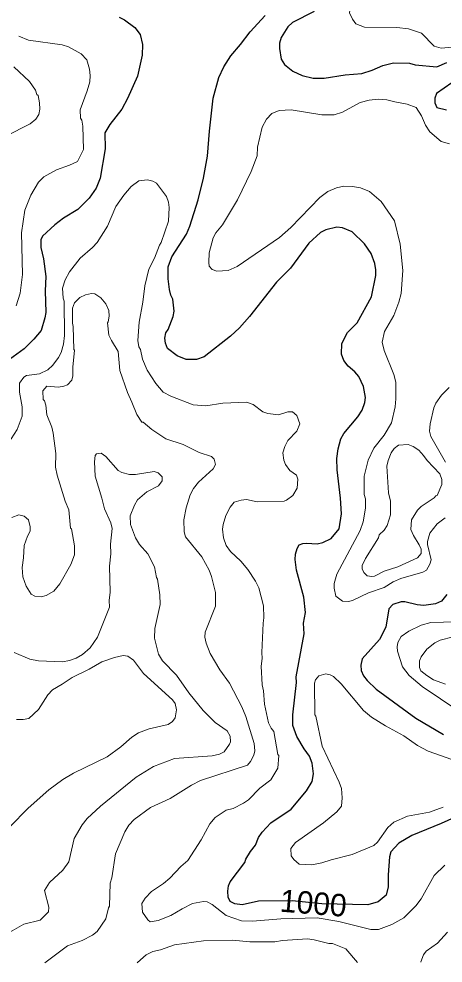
# Model space of a CAD drawing. Extents: x 447.8 to 473.9, y 7733.1 to 7760.8.
# Drawn here: x 467.383 to 468.897, y 7733.127 to 7736.498 of the extents above; entities that cross this region are included whole.
import ezdxf
from ezdxf.enums import TextEntityAlignment as Align

# ---------------------------------------------------------------- set-up
doc = ezdxf.new("R2010")
doc.units = 0
doc.header["$LTSCALE"] = 0.032
doc.layers.add('1', color=7, linetype='Continuous', lineweight=25)
doc.layers.add('2', color=7, linetype='Continuous', lineweight=13)
doc.layers.add('61', color=7, linetype='Continuous')

msp = doc.modelspace()

# ---------------------------------------------------------------- linework, layer by layer
at = {"layer": '1'}
for points in [[(468.208, 7736.4522), (468.262, 7736.5109)], [(468.4364, 7736.5251), (468.359, 7736.4854), (468.3427, 7736.4698), (468.3193, 7736.4314), (468.3136, 7736.4119), (468.3128, 7736.3923), (468.3191, 7736.3545), (468.3312, 7736.3349), (468.3605, 7736.3119), (468.3936, 7736.2967), (468.4329, 7736.2869), (468.4722, 7736.2869), (468.548, 7736.298), (468.6076, 7736.3032), (468.6442, 7736.3147), (468.6819, 7736.3316), (468.7199, 7736.3413), (468.7768, 7736.3398), (468.7972, 7736.3341), (468.8746, 7736.3272), (468.9108, 7736.3429)], [(467.7404, 7736.5048), (467.7593, 7736.4954), (467.7965, 7736.468), (467.8157, 7736.4431), (467.8245, 7736.407), (467.823, 7736.369), (467.8062, 7736.2941), (467.7707, 7736.2144), (467.7502, 7736.1765), (467.7073, 7736.1211), (467.6891, 7736.0917), (467.6906, 7736.0348), (467.6731, 7735.9297), (467.6586, 7735.8941), (467.6339, 7735.8577), (467.5931, 7735.8183), (467.5424, 7735.7871), (467.5114, 7735.7629), (467.4672, 7735.7223), (467.4616, 7735.7096), (467.4614, 7735.6816), (467.4711, 7735.642), (467.4791, 7735.5786), (467.4767, 7735.5273), (467.479, 7735.4497), (467.4759, 7735.4311), (467.4618, 7735.3859), (467.4365, 7735.3546), (467.4019, 7735.3207), (467.3358, 7735.2723)], [(468.0759, 7736.2157), (468.0965, 7736.2886), (468.1148, 7736.3271), (468.1398, 7736.3663), (468.1743, 7736.4065), (468.208, 7736.4522)], [(468.9554, 7736.2885), (468.8741, 7736.2317), (468.8675, 7736.2147), (468.8674, 7736.1981), (468.8744, 7736.1816), (468.9088, 7736.1731)], [(468.1897, 7733.4862), (468.1933, 7733.4981), (468.2095, 7733.5256), (468.2275, 7733.5485), (468.238, 7733.5756), (468.2511, 7733.5947), (468.2825, 7733.6281), (468.3546, 7733.6763), (468.41, 7733.7419), (468.4298, 7733.7752), (468.4345, 7733.8034), (468.4296, 7733.8408), (468.42, 7733.866), (468.4013, 7733.8921), (468.3754, 7733.9363), (468.3608, 7733.9758), (468.3608, 7734.0132), (468.3736, 7734.1286), (468.373, 7734.1497), (468.4008, 7734.3021), (468.3993, 7734.341), (468.4057, 7734.3787), (468.4001, 7734.4333), (468.3735, 7734.5305), (468.3689, 7734.5679), (468.3704, 7734.5872), (468.3762, 7734.6069), (468.3839, 7734.62), (468.3965, 7734.6251), (468.4093, 7734.6267), (468.4477, 7734.6236), (468.4681, 7734.6289), (468.4972, 7734.6431), (468.5259, 7734.6776), (468.5339, 7734.7316), (468.5308, 7734.7875), (468.5193, 7734.8881), (468.5181, 7734.9286), (468.5224, 7734.9636), (468.5322, 7734.9992), (468.5423, 7735.018), (468.5922, 7735.077), (468.6083, 7735.1018), (468.6174, 7735.1281), (468.6197, 7735.147), (468.6131, 7735.1861), (468.5958, 7735.222), (468.5818, 7735.2385), (468.5578, 7735.2587), (468.5424, 7735.2785), (468.534, 7735.301), (468.5355, 7735.339), (468.5558, 7735.3781), (468.59, 7735.4135), (468.6412, 7735.5058), (468.6573, 7735.5827), (468.6573, 7735.6027), (468.653, 7735.6255), (468.6409, 7735.6608), (468.6163, 7735.6954), (468.5724, 7735.7385), (468.5375, 7735.7528), (468.5183, 7735.7545), (468.478, 7735.745), (468.4596, 7735.7356), (468.418, 7735.6979), (468.3527, 7735.6087), (468.3021, 7735.558), (468.2056, 7735.4358), (468.1702, 7735.3956), (468.1377, 7735.3656), (468.0447, 7735.2919), (468.0168, 7735.2818), (467.9795, 7735.2817), (467.9482, 7735.2949), (467.9129, 7735.3217), (467.9062, 7735.3401), (467.904, 7735.3586), (467.9079, 7735.3775), (467.9152, 7735.3893), (467.9334, 7735.4352), (467.9367, 7735.4545), (467.9327, 7735.4979), (467.9249, 7735.5122), (467.9199, 7735.5321), (467.916, 7735.5699), (467.9163, 7735.6136), (467.9287, 7735.6485), (467.981, 7735.7301), (467.9929, 7735.7587), (468.0226, 7735.8527), (468.0418, 7735.9297), (468.0566, 7736.0087), (468.0627, 7736.098), (468.0759, 7736.2157)], [(468.91, 7734.4436), (468.891, 7734.4188), (468.8703, 7734.4095), (468.8282, 7734.404), (468.8046, 7734.4064), (468.76, 7734.4167), (468.7471, 7734.4167), (468.7175, 7734.4074), (468.7039, 7734.3925), (468.693, 7734.3261), (468.67, 7734.2827), (468.6082, 7734.2129), (468.6037, 7734.1904), (468.6045, 7734.1723), (468.6124, 7734.1526), (468.6256, 7734.136), (468.6585, 7734.1047), (468.7994, 7734.0019), (468.8981, 7733.9428)], [(468.9981, 7733.674), (468.8904, 7733.6253), (468.7853, 7733.583), (468.7395, 7733.5555), (468.7106, 7733.5248), (468.7053, 7733.5064), (468.7007, 7733.4421), (468.7014, 7733.3995), (468.6943, 7733.3702), (468.6658, 7733.3464), (468.6285, 7733.3355), (468.464, 7733.339), (468.3587, 7733.3488), (468.2376, 7733.3481), (468.1795, 7733.3356), (468.1533, 7733.3384), (468.1366, 7733.3473), (468.1304, 7733.3629), (468.1292, 7733.3839), (468.1316, 7733.403), (468.1367, 7733.4172), (468.1897, 7733.4862)]]:
    msp.add_lwpolyline(points, dxfattribs=at)
at = {"layer": '2'}
for points in [[(468.6085, 7736.5878), (468.5802, 7736.5583), (468.5657, 7736.5381), (468.5631, 7736.5203), (468.5737, 7736.4975), (468.586, 7736.4805)], [(468.586, 7736.4805), (468.6165, 7736.4688), (468.7315, 7736.468), (468.7741, 7736.4632), (468.8195, 7736.447), (468.8657, 7736.4012), (468.8898, 7736.3943), (468.9285, 7736.3975)], [(467.3822, 7736.4371), (467.417, 7736.4219), (467.5368, 7736.4054), (467.5595, 7736.3989), (467.6051, 7736.3734), (467.6248, 7736.3525), (467.6353, 7736.3189), (467.6377, 7736.2961), (467.6361, 7736.2741), (467.6269, 7736.2414), (467.6018, 7736.1734), (467.6026, 7736.1437), (467.6081, 7736.1366), (467.6115, 7736.1151), (467.6137, 7736.0323), (467.5915, 7735.9896), (467.5631, 7735.9761), (467.5172, 7735.9597), (467.4717, 7735.9341), (467.4534, 7735.9154), (467.425, 7735.8694), (467.4041, 7735.815), (467.3926, 7735.734), (467.3957, 7735.5859), (467.3876, 7735.5186), (467.3731, 7735.4737)], [(467.3361, 7736.0799), (467.4232, 7736.1235), (467.4428, 7736.1399), (467.4541, 7736.1572), (467.4574, 7736.1763), (467.4567, 7736.1983), (467.4515, 7736.2251), (467.4473, 7736.2283), (467.4422, 7736.2436), (467.4202, 7736.2751), (467.3647, 7736.3267)], [(468.0896, 7735.5975), (468.0723, 7735.604), (468.0624, 7735.6157), (468.0604, 7735.6291), (468.0626, 7735.6629), (468.0762, 7735.7163), (468.0862, 7735.7347), (468.1096, 7735.7633), (468.163, 7735.8526), (468.2124, 7735.953), (468.233, 7736.0098), (468.235, 7736.0403), (468.2518, 7736.1121), (468.2668, 7736.1406), (468.2858, 7736.1611), (468.3115, 7736.1707), (468.3548, 7736.1738), (468.4638, 7736.1553), (468.508, 7736.1553), (468.5382, 7736.1648), (468.601, 7736.2001), (468.6334, 7736.2082), (468.6651, 7736.2123), (468.6958, 7736.2098), (468.7244, 7736.2019), (468.7693, 7736.1943), (468.8012, 7736.1821), (468.8201, 7736.1521), (468.8346, 7736.1187), (468.8503, 7736.0947), (468.89, 7736.06), (468.9195, 7736.0519)], [(468.2559, 7734.0995), (468.2509, 7734.1204), (468.2478, 7734.1878), (468.251, 7734.2152), (468.2495, 7734.2358), (468.2543, 7734.3413), (468.2574, 7734.3602), (468.2559, 7734.4028), (468.2392, 7734.4666), (468.2271, 7734.4911), (468.2005, 7734.5329), (468.175, 7734.5624), (468.1387, 7734.5962), (468.1228, 7734.618), (468.1135, 7734.6452), (468.1092, 7734.6763), (468.1116, 7734.6936), (468.1218, 7734.7251), (468.1367, 7734.7555), (468.1517, 7734.773), (468.1758, 7734.7805), (468.1954, 7734.7829), (468.2335, 7734.7743), (468.3292, 7734.7765), (468.3387, 7734.7801), (468.3604, 7734.7963), (468.3762, 7734.8223), (468.3783, 7734.8554), (468.3733, 7734.8689), (468.3499, 7734.8862), (468.334, 7734.9069), (468.3287, 7734.9229), (468.325, 7734.949), (468.332, 7734.9717), (468.3433, 7734.9931), (468.3746, 7735.0262), (468.3854, 7735.0523), (468.3749, 7735.0817), (468.3596, 7735.0949), (468.3434, 7735.0957), (468.3098, 7735.0845), (468.2713, 7735.0893), (468.2537, 7735.0956), (468.2189, 7735.1221), (468.1956, 7735.13), (468.1104, 7735.1261), (468.0506, 7735.1173), (468.0046, 7735.1206), (467.925, 7735.1509), (467.8978, 7735.1651), (467.8717, 7735.197), (467.8411, 7735.2439), (467.8241, 7735.2839), (467.8166, 7735.3179), (467.8115, 7735.3275), (467.8078, 7735.3496), (467.8118, 7735.4153), (467.8254, 7735.4874), (467.8325, 7735.5458), (467.8463, 7735.6047), (467.8673, 7735.6445), (467.8848, 7735.6907), (467.8911, 7735.7003), (467.9165, 7735.776), (467.9191, 7735.8248), (467.9167, 7735.8443), (467.9103, 7735.8636), (467.8746, 7735.9112), (467.8612, 7735.919), (467.8417, 7735.9237), (467.8105, 7735.9206), (467.7842, 7735.9002), (467.7574, 7735.8687), (467.7293, 7735.8286), (467.6987, 7735.7578), (467.662, 7735.7003), (467.6456, 7735.6822), (467.6017, 7735.6439), (467.5639, 7735.5956), (467.548, 7735.567), (467.5383, 7735.537), (467.5407, 7735.5008), (467.5448, 7735.49), (467.5457, 7735.3683), (467.5417, 7735.3364), (467.5334, 7735.3074), (467.5238, 7735.2889), (467.504, 7735.2614), (467.4857, 7735.2454), (467.4566, 7735.2312), (467.4104, 7735.2248), (467.4009, 7735.2186), (467.3847, 7735.1974), (467.3845, 7735.1652), (467.395, 7735.1127)], [(468.6799, 7735.3438), (468.6874, 7735.3824), (468.7215, 7735.4388), (468.7391, 7735.4868), (468.747, 7735.5182), (468.7535, 7735.5994), (468.7433, 7735.6938), (468.7231, 7735.7776), (468.6764, 7735.8462), (468.6338, 7735.8822), (468.6021, 7735.8954), (468.5732, 7735.9004), (468.5432, 7735.9012), (468.516, 7735.8952), (468.4861, 7735.8822), (468.457, 7735.8604), (468.353, 7735.7539), (468.3129, 7735.7181), (468.1617, 7735.6142), (468.1296, 7735.5998), (468.0896, 7735.5975)], [(467.3582, 7734.7179), (467.383, 7734.7276), (467.4021, 7734.7229), (467.4173, 7734.7093), (467.4237, 7734.6852), (467.4229, 7734.6696), (467.4133, 7734.6516), (467.4022, 7734.6181), (467.3998, 7734.5737), (467.3942, 7734.5391), (467.3974, 7734.5058), (467.4083, 7734.4727), (467.4264, 7734.444), (467.4402, 7734.4369), (467.4625, 7734.4353), (467.4798, 7734.4394), (467.5081, 7734.4547), (467.5294, 7734.4807), (467.5685, 7734.55), (467.5816, 7734.5845), (467.5817, 7734.6172), (467.5706, 7734.6773), (467.5672, 7734.6803), (467.5616, 7734.746), (467.5477, 7734.7766), (467.5192, 7734.8693), (467.5136, 7734.8982), (467.515, 7734.9469), (467.5054, 7735.0194), (467.5003, 7735.04), (467.4826, 7735.0849), (467.479, 7735.1197), (467.4741, 7735.1349), (467.4695, 7735.1392), (467.4687, 7735.1706), (467.483, 7735.1868), (467.5244, 7735.1839), (467.5438, 7735.1864), (467.5558, 7735.1917), (467.5719, 7735.2079), (467.5759, 7735.224), (467.5753, 7735.2548), (467.5816, 7735.3158), (467.5785, 7735.318), (467.5768, 7735.4003), (467.5737, 7735.4116), (467.5737, 7735.466), (467.5816, 7735.4842), (467.6005, 7735.5032), (467.6208, 7735.5135), (467.6426, 7735.5173), (467.6538, 7735.5165), (467.6757, 7735.5019), (467.6935, 7735.4814), (467.7045, 7735.4571), (467.7051, 7735.4368), (467.7019, 7735.4167), (467.6989, 7735.413), (467.7037, 7735.3695), (467.713, 7735.3498), (467.7377, 7735.3108), (467.7437, 7735.2435), (467.7703, 7735.164), (467.7863, 7735.1303), (467.8041, 7735.0854), (467.8219, 7735.0585), (467.826, 7735.0579), (467.8569, 7735.0323), (467.9072, 7734.9994), (467.9696, 7734.9786), (468.026, 7734.9505), (468.07, 7734.9356), (468.08, 7734.9267), (468.0841, 7734.9067), (468.0769, 7734.8913), (468.0239, 7734.8438), (468.0067, 7734.8218), (467.9938, 7734.7994)], [(468.7263, 7735.1133), (468.7287, 7735.1418), (468.7278, 7735.2007), (468.7214, 7735.229), (468.6865, 7735.3146), (468.6799, 7735.3438)], [(468.9183, 7735.1822), (468.8912, 7735.1547), (468.8714, 7735.1257), (468.8641, 7735.1098), (468.8506, 7735.0528), (468.849, 7735.0268), (468.8539, 7735.0072), (468.9054, 7734.9152)], [(467.395, 7735.1127), (467.395, 7735.0803), (467.3767, 7735.0321), (467.355, 7734.9987), (467.3041, 7734.9416), (467.2568, 7734.9124)], [(468.9045, 7734.7168), (468.8757, 7734.6959), (468.8503, 7734.6621), (468.8412, 7734.6321), (468.8409, 7734.6217), (468.8545, 7734.5667), (468.8503, 7734.552), (468.8373, 7734.5301), (468.8246, 7734.5224), (468.7468, 7734.5), (468.7184, 7734.4881), (468.6863, 7734.4682), (468.6314, 7734.4487), (468.5737, 7734.4214), (468.5596, 7734.4176), (468.5381, 7734.4189), (468.5147, 7734.4372), (468.5085, 7734.4659), (468.5087, 7734.4829), (468.5181, 7734.5156), (468.6011, 7734.6721), (468.6119, 7734.7023), (468.6205, 7734.7518), (468.6197, 7734.7846), (468.6158, 7734.8004), (468.6158, 7734.8651), (468.6302, 7734.9229), (468.6495, 7734.9661), (468.6865, 7735.0116), (468.7135, 7735.0559), (468.7263, 7735.1133)], [(467.3665, 7734.2358), (467.4215, 7734.2119), (467.4527, 7734.206), (467.5382, 7734.2031), (467.563, 7734.2077), (467.5875, 7734.216), (467.61, 7734.2285), (467.6375, 7734.2522), (467.6639, 7734.2903), (467.7066, 7734.3984), (467.7052, 7734.4214), (467.7084, 7734.4518), (467.706, 7734.5446), (467.7114, 7734.5884), (467.71, 7734.6231), (467.7155, 7734.6788), (467.7105, 7734.6988), (467.6883, 7734.7494), (467.6795, 7734.7875), (467.6554, 7734.8652), (467.6523, 7734.9173), (467.6555, 7734.9392), (467.6602, 7734.9452), (467.6768, 7734.9481), (467.6936, 7734.9356), (467.7372, 7734.8858), (467.7503, 7734.8784), (467.7782, 7734.8721), (467.7988, 7734.8713), (467.8654, 7734.8824), (467.88, 7734.8775), (467.8939, 7734.8636), (467.8941, 7734.8491), (467.8811, 7734.8308), (467.8395, 7734.8094), (467.8064, 7734.7817), (467.7951, 7734.7625), (467.7805, 7734.7236), (467.7808, 7734.6933), (467.7986, 7734.6457), (467.8139, 7734.6214), (467.8427, 7734.5878), (467.8674, 7734.5415), (467.8744, 7734.5043), (467.8782, 7734.4974), (467.8862, 7734.4416), (467.8877, 7734.4072), (467.8687, 7734.3213), (467.8671, 7734.2874), (467.8811, 7734.2305), (467.8958, 7734.2059), (467.9453, 7734.1557), (467.9894, 7734.0916), (468.0404, 7734.0293), (468.0837, 7733.9862), (468.126, 7733.9558), (468.1371, 7733.9369), (468.1379, 7733.9173), (468.1351, 7733.9088), (468.1155, 7733.8812), (468.0995, 7733.8728), (468.0729, 7733.8669), (467.9379, 7733.8573), (467.8633, 7733.8288), (467.8013, 7733.7915), (467.6736, 7733.6871), (467.6263, 7733.643), (467.6082, 7733.6213), (467.5799, 7733.5721), (467.5606, 7733.4883), (467.5398, 7733.4594)], [(467.9938, 7734.7994), (467.9796, 7734.7524), (467.9713, 7734.7097), (467.9728, 7734.6664), (467.978, 7734.6489), (468.0357, 7734.5772)], [(468.0357, 7734.5772), (468.0618, 7734.5297), (468.0706, 7734.507), (468.0851, 7734.4505), (468.085, 7734.401), (468.0482, 7734.3082), (468.0467, 7734.2913), (468.0508, 7734.2694), (468.0654, 7734.2326), (468.1005, 7734.1736), (468.1349, 7734.1271), (468.1787, 7734.0417), (468.1928, 7734.0077), (468.223, 7733.9106), (468.2254, 7733.8855), (468.2213, 7733.8693), (468.2095, 7733.8471), (468.1987, 7733.8342), (468.0316, 7733.7791), (467.9988, 7733.762), (467.9229, 7733.7145), (467.8527, 7733.6825), (467.7947, 7733.6398), (467.7757, 7733.6191), (467.7614, 7733.5954), (467.7282, 7733.5175), (467.7148, 7733.4319), (467.7085, 7733.4121), (467.7068, 7733.3305), (467.7026, 7733.3244), (467.6935, 7733.2852), (467.6621, 7733.2403), (467.6456, 7733.2272), (467.6083, 7733.2076), (467.5569, 7733.1882), (467.476, 7733.1275)], [(468.9439, 7734.3455), (468.8536, 7734.3431), (468.819, 7734.3332), (468.7747, 7734.3127), (468.7469, 7734.293), (468.7353, 7734.2719), (468.7328, 7734.2565), (468.7345, 7734.2403), (468.7518, 7734.1854), (468.7755, 7734.1536), (468.8221, 7734.1143), (468.9534, 7734.0269)], [(468.9331, 7734.2917), (468.8864, 7734.2803), (468.8681, 7734.271), (468.8396, 7734.2479), (468.8194, 7734.2211), (468.813, 7734.2064), (468.8134, 7734.1821), (468.8181, 7734.1704), (468.8391, 7734.1534), (468.8634, 7734.1385), (468.9052, 7734.1235)], [(467.3748, 7733.9972), (467.3978, 7733.9963), (467.4189, 7734.0008), (467.453, 7734.0331), (467.4865, 7734.0844), (467.5029, 7734.1031), (467.5378, 7734.1227), (467.5731, 7734.1469), (467.6343, 7734.1769), (467.6784, 7734.2022), (467.7246, 7734.218), (467.7545, 7734.2251), (467.7715, 7734.2232), (467.7914, 7734.2092), (467.8281, 7734.1615), (467.9313, 7734.067), (467.9407, 7734.0534), (467.9456, 7734.0312), (467.9411, 7734.003), (467.9313, 7733.9897), (467.9154, 7733.9792), (467.8481, 7733.9639), (467.8104, 7733.9488), (467.7863, 7733.9339), (467.7466, 7733.8995), (467.6981, 7733.863), (467.5777, 7733.8051), (467.5393, 7733.7825), (467.4893, 7733.7458), (467.4155, 7733.6806), (467.3506, 7733.6141)], [(468.949, 7733.8467), (468.8438, 7733.8835), (468.8054, 7733.9039), (468.7571, 7733.9381), (468.6913, 7733.9741), (468.6415, 7734.0052), (468.6128, 7734.0285), (468.5329, 7734.1244), (468.5064, 7734.15), (468.4937, 7734.1562), (468.4782, 7734.1593), (468.4537, 7734.1527), (468.4422, 7734.138), (468.4376, 7734.1269), (468.4394, 7734.013), (468.4433, 7734.0084), (468.4656, 7733.902), (468.5258, 7733.7733), (468.534, 7733.7503), (468.5371, 7733.7169), (468.534, 7733.6871), (468.5173, 7733.6674), (468.4696, 7733.6278), (468.3702, 7733.5572), (468.353, 7733.5359), (468.3544, 7733.5105), (468.3641, 7733.4964), (468.3833, 7733.4806), (468.4282, 7733.4782), (468.4637, 7733.4846), (468.4977, 7733.4959), (468.5727, 7733.5143), (468.6496, 7733.5465), (468.6632, 7733.5589), (468.7004, 7733.6109), (468.7218, 7733.6298), (468.7695, 7733.652), (468.8484, 7733.6663), (468.8975, 7733.684)], [(468.3072, 7733.8722), (468.2933, 7733.954), (468.283, 7733.9663), (468.2734, 7733.9851), (468.2599, 7734.0517), (468.2559, 7734.0995)], [(468.9032, 7733.4771), (468.8648, 7733.4394), (468.8187, 7733.3565), (468.8003, 7733.3317), (468.7571, 7733.2892), (468.7146, 7733.2646), (468.6661, 7733.2467), (468.6394, 7733.2465), (468.525, 7733.276), (468.4477, 7733.2881), (468.3184, 7733.2849), (468.2172, 7733.2762), (468.1773, 7733.2779), (468.1227, 7733.2966), (468.0732, 7733.3362), (468.0549, 7733.3456), (468.0421, 7733.3474), (468.003, 7733.3393), (467.9651, 7733.3211), (467.9257, 7733.2966), (467.8802, 7733.279), (467.8514, 7733.2746), (467.8436, 7733.2812), (467.8244, 7733.3088), (467.8222, 7733.3399), (467.8334, 7733.3594), (467.8564, 7733.3824), (467.8988, 7733.4113), (467.9213, 7733.4306), (467.9608, 7733.4725), (467.9854, 7733.4931), (468.0339, 7733.5668), (468.0644, 7733.6243), (468.0831, 7733.6468), (468.1233, 7733.6726), (468.1479, 7733.6787), (468.1849, 7733.6976), (468.2023, 7733.7104), (468.2435, 7733.7512), (468.2817, 7733.7816), (468.3071, 7733.8228), (468.3104, 7733.8679), (468.3072, 7733.8722)], [(467.5398, 7733.4594), (467.4925, 7733.4152), (467.4744, 7733.386), (467.4902, 7733.3266), (467.4886, 7733.3101), (467.4584, 7733.2804)], [(467.4584, 7733.2804), (467.4008, 7733.2657), (467.351, 7733.2376), (467.3342, 7733.2203), (467.3191, 7733.1917), (467.2914, 7733.1551), (467.2838, 7733.1506), (467.2729, 7733.127)], [(468.9123, 7733.2377), (468.8775, 7733.198), (468.8362, 7733.1701), (468.8271, 7733.1561), (468.8178, 7733.1311), (468.8173, 7733.1299)], [(468.5917, 7733.1295), (468.55, 7733.1782), (468.5026, 7733.1965), (468.489, 7733.1968), (468.4365, 7733.2105), (468.4134, 7733.2135), (468.3236, 7733.2079), (468.2965, 7733.2027), (468.2078, 7733.2024), (468.1456, 7733.2087), (468.0414, 7733.2071), (467.9388, 7733.1919), (467.8882, 7733.1744), (467.8612, 7733.168), (467.8376, 7733.1562), (467.8067, 7733.1291), (467.8052, 7733.1281)]]:
    msp.add_lwpolyline(points, dxfattribs=at)
msp.add_lwpolyline([(468.84, 7734.9211), (468.8275, 7734.9399), (468.8103, 7734.9587), (468.7907, 7734.9721), (468.7719, 7734.9785), (468.7376, 7734.9761), (468.723, 7734.9641), (468.7121, 7734.9485), (468.701, 7734.922), (468.6959, 7734.9017), (468.7021, 7734.8066), (468.7095, 7734.7766), (468.7094, 7734.7279), (468.6971, 7734.6895), (468.6862, 7734.6724), (468.6687, 7734.6561), (468.6669, 7734.6454), (468.6205, 7734.5712), (468.6079, 7734.5461), (468.6079, 7734.5342), (468.6139, 7734.5214), (468.6259, 7734.51), (468.6426, 7734.5074), (468.6519, 7734.5088), (468.6862, 7734.5265), (468.735, 7734.5421), (468.8057, 7734.5739), (468.8191, 7734.5891), (468.8185, 7734.6047), (468.8122, 7734.6208), (468.7913, 7734.6533), (468.7825, 7734.6752), (468.7839, 7734.7095), (468.8053, 7734.7443), (468.8188, 7734.7568), (468.8655, 7734.7877), (468.8709, 7734.7952), (468.8755, 7734.797), (468.893, 7734.836), (468.893, 7734.8533), (468.8859, 7734.8742)], close=True, dxfattribs=at)

# ---------------------------------------------------------------- texts
at = {"layer": '61'}
msp.add_text('1000', height=0.08, rotation=355.419, dxfattribs=at).set_placement((468.4309, 7733.3015), align=Align.CENTER)

doc.saveas('drawing.dxf')
